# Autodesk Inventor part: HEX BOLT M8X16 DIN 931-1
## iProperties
Created: 2006-02
Part Number: HEX BOLT M8X16 DIN 931-1
Material: Steel, Mild
Description: Hex-Head Bolt
Document SubType Name: Modeling
Standard: DIN 931-1
Designer: Andy Moles
Standards Organization: DIN
Language: en-US
Size Designation: M8 x 35
Categories: <MemberInstance><Categories><Category DisplayName="Fasteners" InternalName="e4da775c-781d-43d5-af7c-5136215cf5a6" Mnemonic="FSTN"><Category DisplayName="Bolts"
Density: 1 g/cm^3
Author: Andy Moles
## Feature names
1. Body [Revolution]
2. Head [Extrusion]
3. Chamfer1 [Revolution]
4. Chamfer2
